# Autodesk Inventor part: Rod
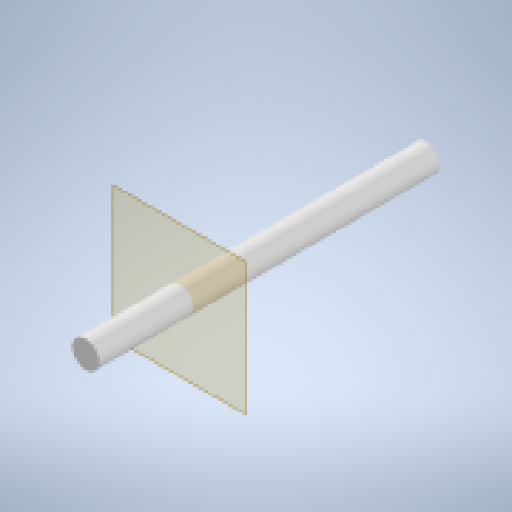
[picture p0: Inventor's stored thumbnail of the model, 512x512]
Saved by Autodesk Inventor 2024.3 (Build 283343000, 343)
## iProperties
Created: 2024-12
Part Number: Rod
Material: Generic
Document SubType Name: Modeling
Designer: ruhr
Density: 1 g/cm^3
Appearance: Default
Author: ruhr
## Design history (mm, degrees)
workplane "Work Plane1"
sketch "Sketch1"
  geometry: C1 r 5 at (0, 0) reference; 1 further point
extrude "Extrusion1" new body sketch "Sketch1" distance "d0" = 35.25; taper "d2" = 0 deg; dims "d1" = 92.25, "d3" = 0
body "Solid1"
node "Reference1"
